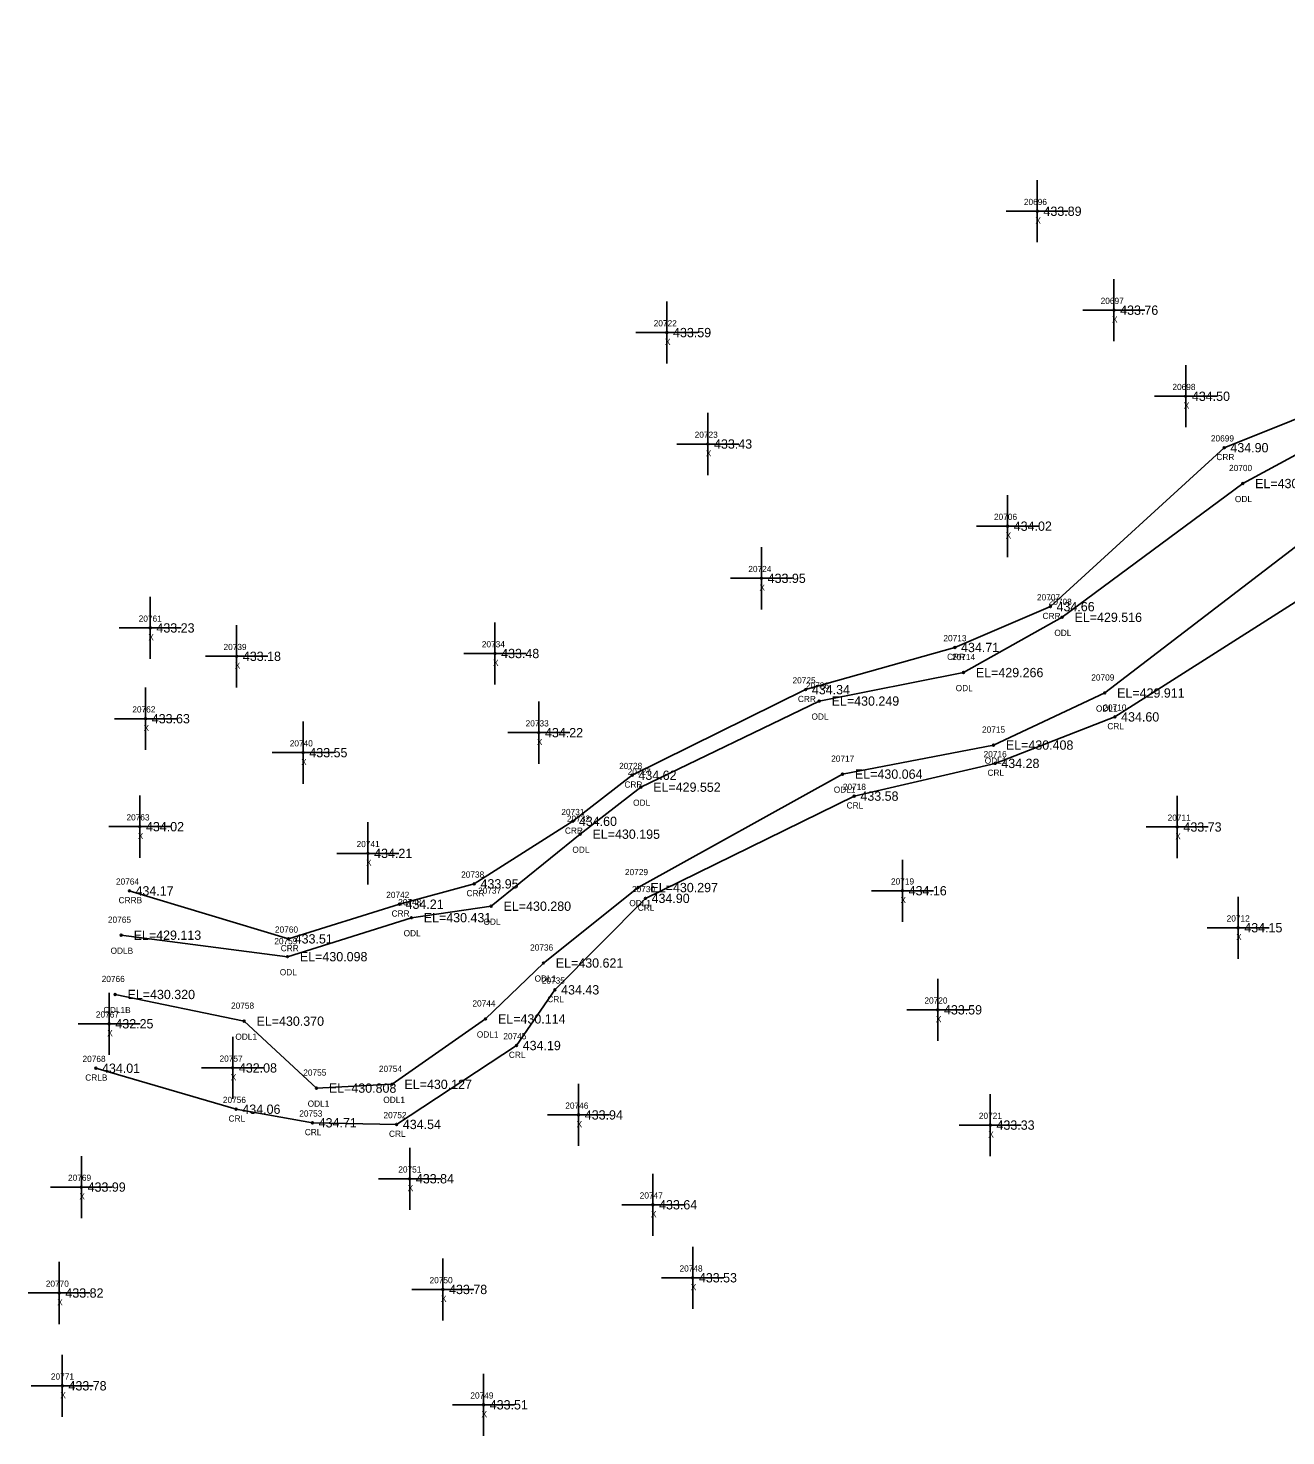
# Model space of a CAD drawing. Extents: x 1613836 to 1615109, y 777151 to 778248.
# Drawn here: x 1614085.4 to 1614288, y 777224.3 to 777451 of the extents above; entities that cross this region are included whole.
import ezdxf

# ---------------------------------------------------------------- set-up
doc = ezdxf.new("R2010")
doc.units = 0
for name, color, linetype in [('RD_EX_H2O', 7, 'Continuous'), ('RD_EX_H2O_txCode', 7, 'Continuous'), ('RD_EX_Misc', 7, 'Continuous'), ('RD_EX_Misc_txCode', 7, 'Continuous'), ('RD_EX_TX_H2O_ELEV', 7, 'Continuous'), ('RD_EX_TX_Misc_ELEV', 7, 'Continuous'), ('RD_SMD_Locator', 7, 'Continuous')]:
    doc.layers.add(name, color=color, linetype=linetype)

msp = doc.modelspace()

# ---------------------------------------------------------------- linework, layer by layer
at = {"layer": 'RD_EX_H2O'}
for points in [[(1614454.05, 777670.72), (1614436.75, 777625.46), (1614428.25, 777606.48), (1614422.27, 777582.64), (1614421.12, 777572.72), (1614422.32, 777559.44), (1614418.89, 777533.48), (1614401.74, 777483.1), (1614391.89, 777467.73), (1614349.64, 777429.15), (1614339.78, 777409.85), (1614335.95, 777396.86), (1614325.72, 777389.21), (1614290.49, 777368.16), (1614258.86, 777343.9), (1614240.94, 777335.51), (1614216.63, 777330.83), (1614183.69, 777312.56), (1614168.44, 777300.41), (1614159.13, 777291.4), (1614144.06, 777280.87), (1614131.88, 777280.26), (1614120.23, 777291.04), (1614099.45, 777295.34)], [(1614459.87, 777668.19), (1614440.89, 777623.61), (1614431.44, 777603.44), (1614426.49, 777580.47), (1614427.73, 777573.1), (1614426.99, 777558.49), (1614422.1, 777533.28), (1614405.02, 777481.5), (1614394.67, 777464.56), (1614354.26, 777425.05), (1614343.94, 777405.8), (1614336.19, 777392.32), (1614327.17, 777384), (1614294.72, 777361.79), (1614260.51, 777340.05), (1614241.21, 777332.56), (1614218.51, 777327.29), (1614184.87, 777310.82), (1614170.3, 777296.09), (1614164.11, 777287.12), (1614144.8, 777274.41), (1614131.24, 777274.67), (1614118.95, 777276.86), (1614096.34, 777283.46)], [(1614355.46, 777459.21), (1614337.74, 777435.91), (1614315.35, 777404.89), (1614299.82, 777392.07), (1614278.11, 777383.41), (1614250.11, 777357.81), (1614234.72, 777351.23), (1614210.69, 777344.44), (1614182.75, 777330.65), (1614173.16, 777323.23), (1614157.31, 777313.16), (1614145.24, 777309.88), (1614127.38, 777304.3), (1614101.74, 777312.03)], [(1614356.26, 777456.14), (1614340.53, 777434.54), (1614317.92, 777402.32), (1614300.86, 777388.3), (1614281.09, 777377.64), (1614252, 777356.09), (1614236.11, 777347.19), (1614212.88, 777342.6), (1614184.13, 777328.73), (1614174.35, 777321.16), (1614160.03, 777309.56), (1614147.17, 777307.71), (1614127.22, 777301.43), (1614100.44, 777304.89)]]:
    msp.add_lwpolyline(points, dxfattribs=at)
at = {"layer": 'RD_EX_Misc'}
for p, q in [((1614248, 777416.49), (1614248, 777426.49)), ((1614243, 777421.49), (1614253, 777421.49)), ((1614260.35, 777400.56), (1614260.35, 777410.56)), ((1614188.33, 777396.95), (1614188.33, 777406.95)), ((1614255.35, 777405.56), (1614265.35, 777405.56)), ((1614183.33, 777401.95), (1614193.33, 777401.95)), ((1614271.91, 777386.69), (1614271.91, 777396.69)), ((1614266.91, 777391.69), (1614276.91, 777391.69)), ((1614194.93, 777379), (1614194.93, 777389)), ((1614189.93, 777384), (1614199.93, 777384)), ((1614243.21, 777365.77), (1614243.21, 777375.77)), ((1614238.21, 777370.77), (1614248.21, 777370.77)), ((1614203.57, 777357.37), (1614203.57, 777367.37)), ((1614198.57, 777362.37), (1614208.57, 777362.37)), ((1614105.11, 777349.38), (1614105.11, 777359.38)), ((1614160.64, 777345.26), (1614160.64, 777355.26)), ((1614100.11, 777354.38), (1614110.11, 777354.38)), ((1614119.03, 777344.81), (1614119.03, 777354.81)), ((1614114.03, 777349.81), (1614124.03, 777349.81)), ((1614155.64, 777350.26), (1614165.64, 777350.26)), ((1614104.36, 777334.76), (1614104.36, 777344.76)), ((1614167.7, 777332.51), (1614167.7, 777342.51)), ((1614099.36, 777339.76), (1614109.36, 777339.76)), ((1614129.74, 777329.29), (1614129.74, 777339.29)), ((1614162.7, 777337.51), (1614172.7, 777337.51)), ((1614124.74, 777334.29), (1614134.74, 777334.29)), ((1614103.42, 777317.37), (1614103.42, 777327.37)), ((1614270.55, 777317.32), (1614270.55, 777327.32)), ((1614098.42, 777322.37), (1614108.42, 777322.37)), ((1614140.18, 777313.07), (1614140.18, 777323.07)), ((1614265.55, 777322.32), (1614275.55, 777322.32)), ((1614135.18, 777318.07), (1614145.18, 777318.07)), ((1614226.28, 777307.05), (1614226.28, 777317.05)), ((1614221.28, 777312.05), (1614231.28, 777312.05)), ((1614280.35, 777301.09), (1614280.35, 777311.09)), ((1614275.35, 777306.09), (1614285.35, 777306.09)), ((1614231.97, 777287.87), (1614231.97, 777297.87)), ((1614098.49, 777285.62), (1614098.49, 777295.62)), ((1614226.97, 777292.87), (1614236.97, 777292.87)), ((1614093.49, 777290.62), (1614103.49, 777290.62)), ((1614118.39, 777278.51), (1614118.39, 777288.51)), ((1614113.39, 777283.51), (1614123.39, 777283.51)), ((1614174.11, 777270.94), (1614174.11, 777280.94)), ((1614240.43, 777269.3), (1614240.43, 777279.3)), ((1614169.11, 777275.94), (1614179.11, 777275.94)), ((1614235.43, 777274.3), (1614245.43, 777274.3)), ((1614094.02, 777259.32), (1614094.02, 777269.32)), ((1614146.9, 777260.66), (1614146.9, 777270.66)), ((1614089.02, 777264.32), (1614099.02, 777264.32)), ((1614141.9, 777265.66), (1614151.9, 777265.66)), ((1614186.08, 777256.47), (1614186.08, 777266.47)), ((1614181.08, 777261.47), (1614191.08, 777261.47)), ((1614192.49, 777244.71), (1614192.49, 777254.71)), ((1614090.44, 777242.26), (1614090.44, 777252.26)), ((1614152.25, 777242.83), (1614152.25, 777252.83)), ((1614187.49, 777249.71), (1614197.49, 777249.71)), ((1614085.44, 777247.26), (1614095.44, 777247.26)), ((1614147.25, 777247.83), (1614157.25, 777247.83)), ((1614090.94, 777227.31), (1614090.94, 777237.31)), ((1614158.8, 777224.25), (1614158.8, 777234.25)), ((1614085.94, 777232.31), (1614095.94, 777232.31)), ((1614153.8, 777229.25), (1614163.8, 777229.25))]:
    msp.add_line(p, q, dxfattribs=at)
at = {"layer": 'RD_SMD_Locator'}
for centre in [(1614248, 777421.49), (1614260.35, 777405.56), (1614188.33, 777401.95), (1614271.91, 777391.69), (1614194.93, 777384), (1614278.11, 777383.41), (1614281.09, 777377.64), (1614243.21, 777370.77), (1614203.57, 777362.37), (1614250.11, 777357.81), (1614252, 777356.09), (1614105.11, 777354.38), (1614234.72, 777351.23), (1614119.03, 777349.81), (1614160.64, 777350.26), (1614236.11, 777347.19), (1614210.69, 777344.44), (1614258.86, 777343.9), (1614212.88, 777342.6), (1614104.36, 777339.76), (1614260.51, 777340.05), (1614167.7, 777337.51), (1614240.94, 777335.51), (1614129.74, 777334.29), (1614241.21, 777332.56), (1614182.75, 777330.65), (1614216.63, 777330.83), (1614184.13, 777328.73), (1614218.51, 777327.29), (1614173.16, 777323.23), (1614103.42, 777322.37), (1614174.35, 777321.16), (1614270.55, 777322.32), (1614140.18, 777318.07), (1614101.74, 777312.03), (1614157.31, 777313.16), (1614183.69, 777312.56), (1614226.28, 777312.05), (1614145.24, 777309.88), (1614160.03, 777309.56), (1614184.87, 777310.82), (1614147.17, 777307.71), (1614280.35, 777306.09), (1614100.44, 777304.89), (1614127.38, 777304.3), (1614127.22, 777301.43), (1614168.44, 777300.41), (1614170.3, 777296.09), (1614099.45, 777295.34), (1614159.13, 777291.4), (1614231.97, 777292.87), (1614098.49, 777290.62), (1614120.23, 777291.04), (1614164.11, 777287.12), (1614096.34, 777283.46), (1614118.39, 777283.51), (1614131.88, 777280.26), (1614144.06, 777280.87), (1614118.95, 777276.86), (1614174.11, 777275.94), (1614131.24, 777274.67), (1614144.8, 777274.41), (1614240.43, 777274.3), (1614094.02, 777264.32), (1614146.9, 777265.66), (1614186.08, 777261.47), (1614192.49, 777249.71), (1614090.44, 777247.26), (1614152.25, 777247.83), (1614090.94, 777232.31), (1614158.8, 777229.25)]:
    msp.add_circle(centre, 0.15, dxfattribs=at)

# ---------------------------------------------------------------- texts
at = {"layer": 'RD_EX_H2O_txCode'}
for s, p in [('20699', (1614275.97, 777384.41)), ('CRR', (1614276.86, 777381.41)), ('20700', (1614278.89, 777379.64)), ('ODL', (1614279.84, 777374.64)), ('20707', (1614247.95, 777358.81)), ('20708', (1614249.84, 777358.09)), ('CRR', (1614248.85, 777355.81)), ('20713', (1614232.88, 777352.23)), ('ODL', (1614250.75, 777353.09)), ('CRR', (1614233.47, 777349.23)), ('20714', (1614234.27, 777349.19)), ('20725', (1614208.57, 777345.44)), ('20709', (1614256.7, 777345.9)), ('20726', (1614210.73, 777344.6)), ('ODL', (1614234.86, 777344.19)), ('CRR', (1614209.44, 777342.44)), ('ODL1', (1614257.45, 777340.9)), ('20710', (1614258.64, 777341.05)), ('ODL', (1614211.63, 777339.6)), ('20715', (1614239.1, 777337.51)), ('CRL', (1614259.29, 777338.05)), ('20728', (1614180.64, 777331.65)), ('20717', (1614214.8, 777332.83)), ('20716', (1614239.35, 777333.56)), ('ODL1', (1614239.53, 777332.51)), ('20727', (1614182.02, 777330.73)), ('CRL', (1614239.98, 777330.56)), ('CRR', (1614181.5, 777328.65)), ('ODL1', (1614215.22, 777327.83)), ('20718', (1614216.68, 777328.29)), ('ODL', (1614182.89, 777325.73)), ('CRL', (1614217.29, 777325.29)), ('20731', (1614171.33, 777324.23)), ('20732', (1614172.23, 777323.16)), ('CRR', (1614171.91, 777321.23)), ('ODL', (1614173.11, 777318.16)), ('20738', (1614155.19, 777314.16)), ('20729', (1614181.58, 777314.56)), ('20764', (1614099.59, 777313.03)), ('CRR', (1614156.06, 777311.16)), ('20737', (1614157.92, 777311.56)), ('20730', (1614182.71, 777311.82)), ('CRRB', (1614100.01, 777310.03)), ('20742', (1614143.12, 777310.88)), ('20743', (1614145.05, 777309.71)), ('ODL1', (1614182.28, 777309.56)), ('CRL', (1614183.64, 777308.82)), ('20765', (1614098.29, 777306.89)), ('CRR', (1614143.99, 777307.88)), ('ODL', (1614158.79, 777306.56)), ('20760', (1614125.2, 777305.3)), ('ODL', (1614145.93, 777304.71)), ('ODLB', (1614098.72, 777301.89)), ('20759', (1614125.1, 777303.43)), ('CRR', (1614126.13, 777302.3)), ('20736', (1614166.3, 777302.41)), ('20766', (1614097.29, 777297.34)), ('ODL', (1614125.98, 777298.43)), ('ODL1', (1614167.03, 777297.41)), ('20735', (1614168.18, 777297.09)), ('20758', (1614118.12, 777293.04)), ('20744', (1614157.01, 777293.4)), ('CRL', (1614169.07, 777294.09)), ('ODL1B', (1614097.57, 777292.34)), ('ODL1', (1614157.72, 777288.4)), ('ODL1', (1614118.82, 777288.04)), ('20745', (1614161.99, 777288.12)), ('20768', (1614094.2, 777284.46)), ('CRL', (1614162.88, 777285.12)), ('CRLB', (1614094.64, 777281.46)), ('20755', (1614129.76, 777282.26)), ('20754', (1614141.95, 777282.87)), ('20756', (1614116.81, 777277.86)), ('ODL1', (1614130.47, 777277.26)), ('ODL1', (1614142.65, 777277.87)), ('CRL', (1614117.72, 777274.86)), ('20753', (1614129.12, 777275.67)), ('20752', (1614142.68, 777275.41)), ('CRL', (1614130.01, 777272.67)), ('CRL', (1614143.57, 777272.41))]:
    msp.add_text(s, height=1, dxfattribs=at).set_placement(p)
at = {"layer": 'RD_EX_Misc_txCode'}
for s, p in [('20696', (1614245.84, 777422.49)), ('X', (1614247.69, 777419.49)), ('20697', (1614258.21, 777406.56)), ('20722', (1614186.21, 777402.95)), ('X', (1614260.04, 777403.56)), ('X', (1614188.02, 777399.95)), ('20698', (1614269.77, 777392.69)), ('X', (1614271.6, 777389.69)), ('20723', (1614192.81, 777385)), ('X', (1614194.61, 777382)), ('20706', (1614241.03, 777371.77)), ('X', (1614242.9, 777368.77)), ('20724', (1614201.45, 777363.37)), ('X', (1614203.25, 777360.37)), ('20761', (1614103.25, 777355.38)), ('X', (1614104.8, 777352.38)), ('20739', (1614116.91, 777350.81)), ('20734', (1614158.52, 777351.26)), ('X', (1614118.72, 777347.81)), ('X', (1614160.33, 777348.26)), ('20762', (1614102.22, 777340.76)), ('20733', (1614165.58, 777338.51)), ('X', (1614104.04, 777337.76)), ('20740', (1614127.58, 777335.29)), ('X', (1614167.39, 777335.51)), ('X', (1614129.42, 777332.29)), ('20763', (1614101.28, 777323.37)), ('20711', (1614269, 777323.32)), ('X', (1614103.11, 777320.37)), ('X', (1614270.23, 777320.32)), ('20741', (1614138.35, 777319.07)), ('X', (1614139.87, 777316.07)), ('20719', (1614224.44, 777313.05)), ('X', (1614225.96, 777310.05)), ('20712', (1614278.51, 777307.09)), ('X', (1614280.03, 777304.09)), ('20720', (1614229.82, 777293.87)), ('20767', (1614096.35, 777291.62)), ('X', (1614231.66, 777290.87)), ('X', (1614098.18, 777288.62)), ('20757', (1614116.27, 777284.51)), ('X', (1614118.08, 777281.51)), ('20746', (1614171.97, 777276.94)), ('20721', (1614238.59, 777275.3)), ('X', (1614173.79, 777273.94)), ('X', (1614240.11, 777272.3)), ('20751', (1614145.07, 777266.66)), ('20769', (1614091.87, 777265.32)), ('X', (1614146.59, 777263.66)), ('X', (1614093.7, 777262.32)), ('20747', (1614183.96, 777262.47)), ('X', (1614185.76, 777259.47)), ('20748', (1614190.37, 777250.71)), ('20770', (1614088.28, 777248.26)), ('20750', (1614150.1, 777248.83)), ('X', (1614192.18, 777247.71)), ('X', (1614090.13, 777245.26)), ('X', (1614151.94, 777245.83)), ('20771', (1614089.11, 777233.31)), ('X', (1614090.63, 777230.31)), ('20749', (1614156.68, 777230.25)), ('X', (1614158.48, 777227.25))]:
    msp.add_text(s, height=1, dxfattribs=at).set_placement(p)
at = {"layer": 'RD_EX_TX_H2O_ELEV'}
for s, p in [('434.90', (1614279.11, 777382.66)), ('EL=430.157', (1614283.09, 777376.89)), ('434.66', (1614251.11, 777357.06)), ('EL=429.516', (1614254, 777355.34)), ('434.71', (1614235.72, 777350.48)), ('EL=429.266', (1614238.11, 777346.44)), ('434.34', (1614211.69, 777343.69)), ('EL=429.911', (1614260.86, 777343.15)), ('EL=430.249', (1614214.88, 777341.85)), ('434.60', (1614261.51, 777339.3)), ('EL=430.408', (1614242.94, 777334.76)), ('434.28', (1614242.21, 777331.81)), ('434.62', (1614183.75, 777329.9)), ('EL=430.064', (1614218.63, 777330.08)), ('EL=429.552', (1614186.13, 777327.98)), ('433.58', (1614219.51, 777326.54)), ('434.60', (1614174.16, 777322.48)), ('EL=430.195', (1614176.35, 777320.41)), ('434.17', (1614102.74, 777311.28)), ('433.95', (1614158.31, 777312.41)), ('EL=430.297', (1614185.69, 777311.81)), ('434.21', (1614146.24, 777309.13)), ('EL=430.280', (1614162.03, 777308.81)), ('434.90', (1614185.87, 777310.07)), ('EL=430.431', (1614149.17, 777306.96)), ('EL=429.113', (1614102.44, 777304.14)), ('433.51', (1614128.38, 777303.55)), ('EL=430.098', (1614129.22, 777300.68)), ('EL=430.621', (1614170.44, 777299.66)), ('EL=430.320', (1614101.45, 777294.59)), ('434.43', (1614171.3, 777295.34)), ('EL=430.370', (1614122.23, 777290.29)), ('EL=430.114', (1614161.13, 777290.65)), ('434.19', (1614165.11, 777286.37)), ('434.01', (1614097.34, 777282.71)), ('EL=430.808', (1614133.88, 777279.51)), ('EL=430.127', (1614146.06, 777280.12)), ('434.06', (1614119.95, 777276.11)), ('434.71', (1614132.24, 777273.92)), ('434.54', (1614145.8, 777273.66))]:
    msp.add_text(s, height=1.5, dxfattribs=at).set_placement(p)
at = {"layer": 'RD_EX_TX_Misc_ELEV'}
for s, p in [('433.89', (1614249, 777420.74)), ('433.76', (1614261.35, 777404.81)), ('433.59', (1614189.33, 777401.2)), ('434.50', (1614272.91, 777390.94)), ('433.43', (1614195.93, 777383.25)), ('434.02', (1614244.21, 777370.02)), ('433.95', (1614204.57, 777361.62)), ('433.23', (1614106.11, 777353.63)), ('433.18', (1614120.03, 777349.06)), ('433.48', (1614161.64, 777349.51)), ('433.63', (1614105.36, 777339.01)), ('434.22', (1614168.7, 777336.76)), ('433.55', (1614130.74, 777333.54)), ('434.02', (1614104.42, 777321.62)), ('433.73', (1614271.55, 777321.57)), ('434.21', (1614141.18, 777317.32)), ('434.16', (1614227.28, 777311.3)), ('434.15', (1614281.35, 777305.34)), ('433.59', (1614232.97, 777292.12)), ('432.25', (1614099.49, 777289.87)), ('432.08', (1614119.39, 777282.76)), ('433.94', (1614175.11, 777275.19)), ('433.33', (1614241.43, 777273.55)), ('433.99', (1614095.02, 777263.57)), ('433.84', (1614147.9, 777264.91)), ('433.64', (1614187.08, 777260.72)), ('433.78', (1614153.25, 777247.08)), ('433.53', (1614193.49, 777248.96)), ('433.82', (1614091.44, 777246.51)), ('433.78', (1614091.94, 777231.56)), ('433.51', (1614159.8, 777228.5))]:
    msp.add_text(s, height=1.5, dxfattribs=at).set_placement(p)

doc.saveas('drawing.dxf')
